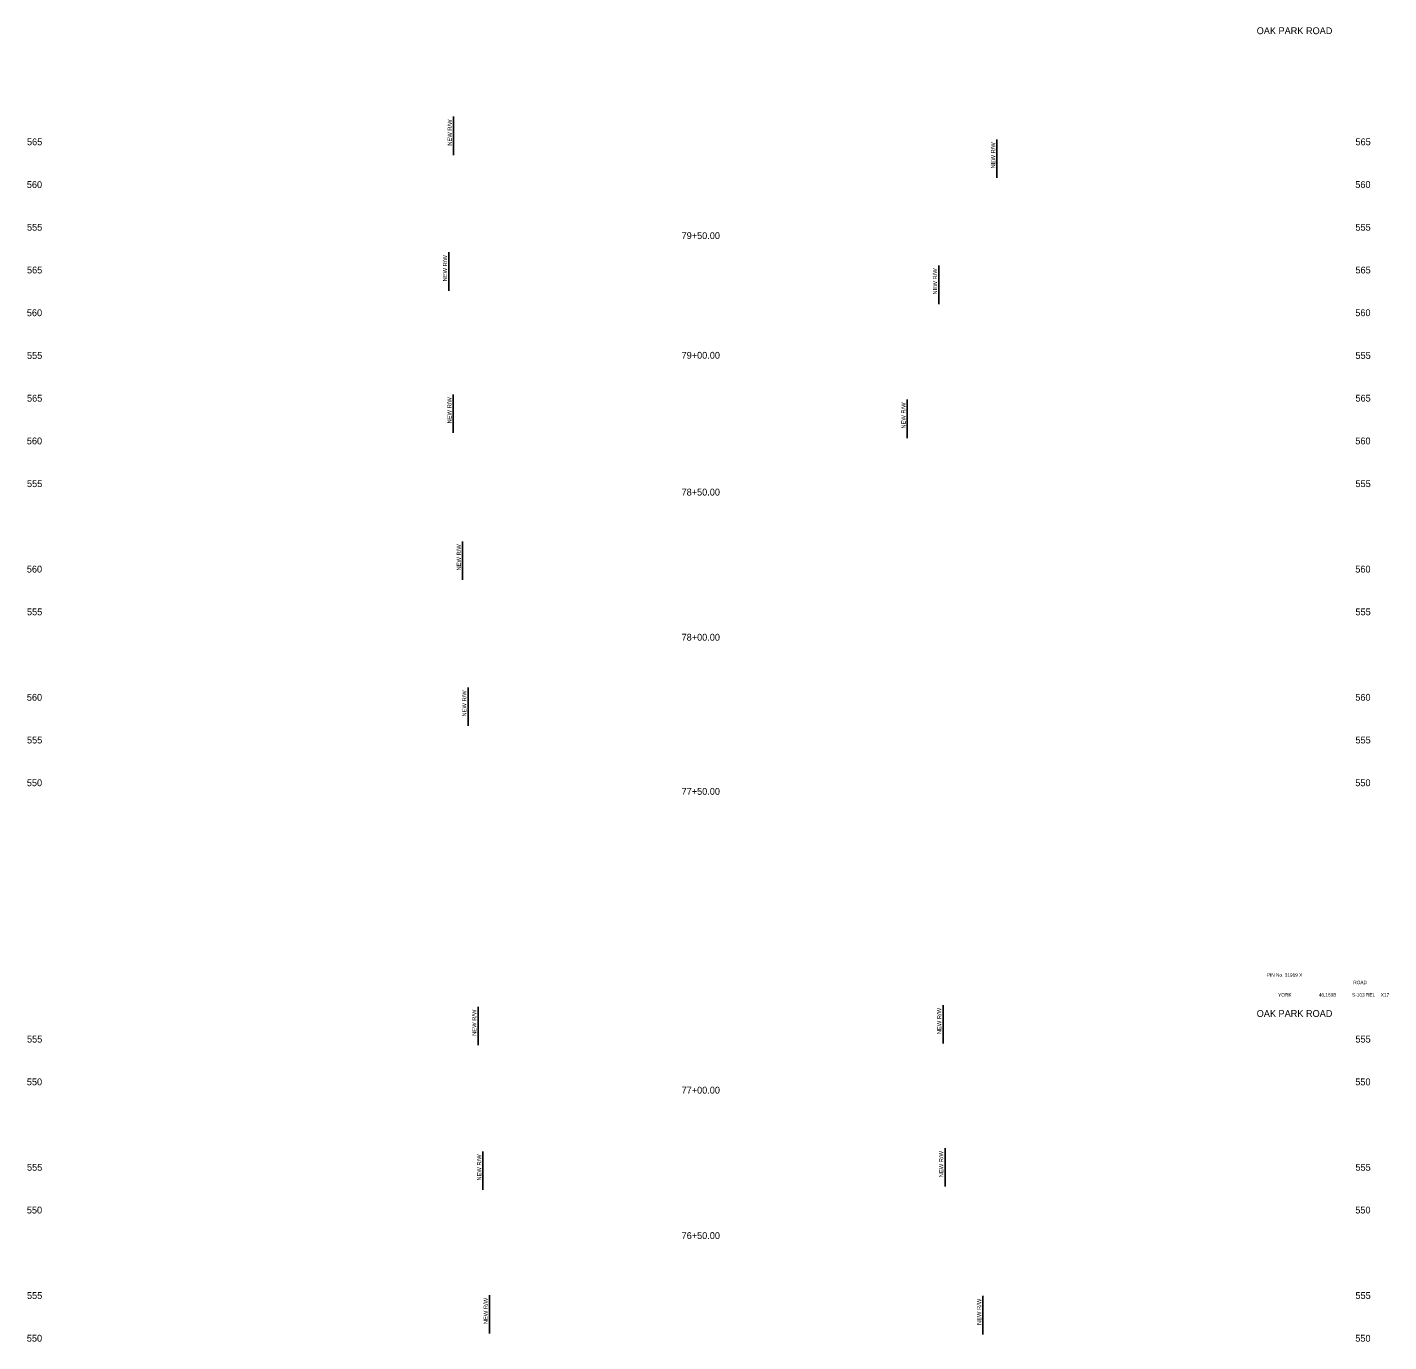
# Model space of a CAD drawing. Extents: x 1001 to 1161, y 1005 to 3518.
# Drawn here: x 1001.2 to 1160.6, y 2900.1 to 3053.9 of the extents above; entities that cross this region are included whole.
import ezdxf

# ---------------------------------------------------------------- set-up
doc = ezdxf.new("R2010")
doc.units = 0
for name, color, linetype in [('RD_SHT_TX', 7, 'Continuous'), ('RD_XS_NewRW', 7, 'Continuous'), ('RD_XS_TX_Elev_EX', 7, 'Continuous'), ('RD_XS_TX_Station', 7, 'Continuous')]:
    doc.layers.add(name, color=color, linetype=linetype)

msp = doc.modelspace()

# ---------------------------------------------------------------- linework, layer by layer
at = {"layer": 'RD_XS_NewRW'}
for p, q in [((1051.09, 3043.45), (1051.09, 3038.95)), ((1114.69, 3040.78), (1114.69, 3036.28)), ((1050.53, 3027.57), (1050.53, 3023.07)), ((1107.89, 3026.02), (1107.89, 3021.52)), ((1051.05, 3010.94), (1051.05, 3006.44)), ((1104.2, 3010.34), (1104.2, 3005.84)), ((1052.15, 2993.74), (1052.15, 2989.24)), ((1052.79, 2976.65), (1052.79, 2972.15)), ((1053.96, 2939.29), (1053.96, 2934.79)), ((1108.38, 2939.48), (1108.38, 2934.98)), ((1054.53, 2922.35), (1054.53, 2917.85)), ((1108.62, 2922.74), (1108.62, 2918.24)), ((1055.3, 2905.54), (1055.3, 2901.04)), ((1113.05, 2905.45), (1113.05, 2900.95))]:
    msp.add_line(p, q, dxfattribs=at)

# ---------------------------------------------------------------- texts
at = {"layer": 'RD_SHT_TX'}
for s, height, p in [('OAK PARK ROAD', 0.8, (1145.1, 3053.1)), ('PIN No. 31919 X', 0.4, (1146.29, 2942.8)), ('ROAD', 0.4, (1156.41, 2941.93)), ('YORK', 0.4, (1147.61, 2940.48)), ('46.169B', 0.4, (1152.37, 2940.48)), ('S-103 REL', 0.4, (1156.26, 2940.48)), ('X17', 0.4, (1159.63, 2940.48)), ('OAK PARK ROAD', 0.8, (1145.1, 2938.1))]:
    msp.add_text(s, height=height, dxfattribs=at).set_placement(p)
at = {"layer": 'RD_XS_NewRW'}
for p in [(1050.89, 3040.05), (1114.49, 3037.38), (1050.33, 3024.17), (1107.69, 3022.63), (1050.85, 3007.55), (1104, 3006.94), (1051.95, 2990.34), (1052.59, 2973.25), (1053.76, 2935.89), (1108.18, 2936.08), (1054.33, 2918.95), (1108.41, 2919.34), (1055.1, 2902.15), (1112.85, 2902.05)]:
    msp.add_text('NEW R/W ', height=0.488, rotation=90, dxfattribs=at).set_placement(p)
at = {"layer": 'RD_XS_TX_Elev_EX'}
for s, p in [('565', (1001.16, 3040.1)), ('565', (1156.66, 3040.1)), ('560', (1001.14, 3035.1)), ('560', (1156.64, 3035.1)), ('555', (1001.16, 3030.1)), ('555', (1156.66, 3030.1)), ('565', (1001.16, 3025.1)), ('565', (1156.66, 3025.1)), ('560', (1001.14, 3020.1)), ('560', (1156.64, 3020.1)), ('555', (1001.16, 3015.1)), ('555', (1156.66, 3015.1)), ('565', (1001.16, 3010.1)), ('565', (1156.66, 3010.1)), ('560', (1001.14, 3005.1)), ('560', (1156.64, 3005.1)), ('555', (1001.16, 3000.1)), ('555', (1156.66, 3000.1)), ('560', (1001.14, 2990.1)), ('560', (1156.64, 2990.1)), ('555', (1001.16, 2985.1)), ('555', (1156.66, 2985.1)), ('560', (1001.14, 2975.1)), ('560', (1156.64, 2975.1)), ('555', (1001.16, 2970.1)), ('555', (1156.66, 2970.1)), ('550', (1001.14, 2965.1)), ('550', (1156.64, 2965.1)), ('555', (1001.16, 2935.1)), ('555', (1156.66, 2935.1)), ('550', (1001.14, 2930.1)), ('550', (1156.64, 2930.1)), ('555', (1001.16, 2920.1)), ('555', (1156.66, 2920.1)), ('550', (1001.14, 2915.1)), ('550', (1156.64, 2915.1)), ('555', (1001.16, 2905.1)), ('555', (1156.66, 2905.1)), ('550', (1001.14, 2900.1)), ('550', (1156.64, 2900.1))]:
    msp.add_text(s, height=0.8, dxfattribs=at).set_placement(p)
at = {"layer": 'RD_XS_TX_Station'}
for s, p in [('79+50.00', (1077.78, 3029.12)), ('79+00.00', (1077.78, 3015.12)), ('78+50.00', (1077.78, 2999.11)), ('78+00.00', (1077.78, 2982.13)), ('77+50.00', (1077.78, 2964.09)), ('77+00.00', (1077.78, 2929.13)), ('76+50.00', (1077.78, 2912.11))]:
    msp.add_text(s, height=0.8, dxfattribs=at).set_placement(p)

doc.saveas('drawing.dxf')
